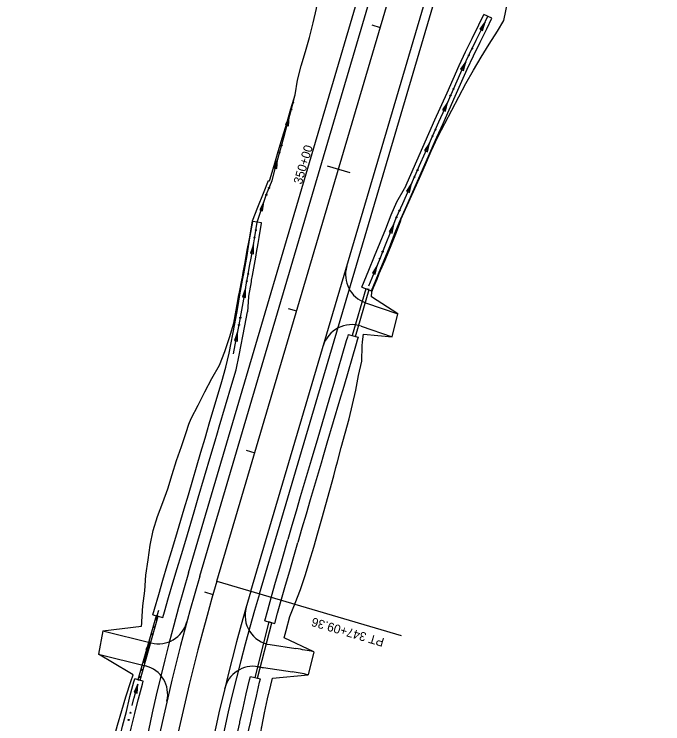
# Model space of a CAD drawing. Extents: x 948761 to 996004, y 1858548 to 1925175.
# Drawn here: x 960907.5 to 961346.2, y 1905677.2 to 1906157.3 of the extents above; entities that cross this region are included whole.
import ezdxf

# ---------------------------------------------------------------- set-up
doc = ezdxf.new("R2010")
doc.units = 0
for name, color, linetype in [('62', 7, 'Continuous'), ('R_Drainage', 7, 'Continuous'), ('R_Horz Alg', 7, 'Continuous'), ('R_Horz Alg Annot', 7, 'Continuous'), ('R_Proposed Const Limits', 7, 'Continuous'), ('R_Proposed Road', 7, 'Continuous')]:
    doc.layers.add(name, color=color, linetype=linetype)

msp = doc.modelspace()

# ---------------------------------------------------------------- linework, layer by layer
at = {"layer": '62'}
for p, q in [((961230.5, 1906154.53), (961225.1, 1906157.14)), ((961225.97, 1906152.06), (961222.4, 1906147.12)), ((961224.31, 1906146.2), (961225.97, 1906152.06)), ((961222.4, 1906147.12), (961224.31, 1906146.2)), ((961212.92, 1906125), (961209.4, 1906120.03)), ((961211.31, 1906119.13), (961212.92, 1906125)), ((961209.4, 1906120.03), (961211.31, 1906119.13)), ((961200.62, 1906097.6), (961197.21, 1906092.55)), ((961199.14, 1906091.69), (961200.62, 1906097.6)), ((961197.21, 1906092.55), (961199.14, 1906091.69)), ((961093.58, 1906087.87), (961090.99, 1906082.36)), ((961093.03, 1906081.81), (961093.58, 1906087.87)), ((961090.99, 1906082.36), (961093.03, 1906081.81)), ((961188.42, 1906070.15), (961185.02, 1906065.1)), ((961186.95, 1906064.24), (961188.42, 1906070.15)), ((961185.02, 1906065.1), (961186.95, 1906064.24)), ((961085.69, 1906058.89), (961083.13, 1906053.36)), ((961085.18, 1906052.82), (961085.69, 1906058.89)), ((961083.13, 1906053.36), (961085.18, 1906052.82)), ((961176.28, 1906042.68), (961172.91, 1906037.6)), ((961174.85, 1906036.75), (961176.28, 1906042.68)), ((961166.4, 1906030.35), (961171.51, 1906039.27)), ((961172.91, 1906037.6), (961174.85, 1906036.75)), ((961076.46, 1906030.36), (961073.55, 1906025)), ((961075.56, 1906024.33), (961076.46, 1906030.36)), ((961073.55, 1906025), (961075.56, 1906024.33)), ((961074.83, 1906016.04), (961068.87, 1906017.04)), ((961164.25, 1906015.16), (961161.09, 1906009.95)), ((961163.06, 1906009.18), (961164.25, 1906015.16)), ((961161.09, 1906009.95), (961163.06, 1906009.18)), ((961069.28, 1906001.29), (961067.25, 1905995.54)), ((961069.34, 1905995.19), (961069.28, 1906001.29)), ((961067.25, 1905995.54), (961069.34, 1905995.19)), ((961152.99, 1905987.31), (961149.75, 1905982.15)), ((961151.71, 1905981.35), (961152.99, 1905987.31)), ((961149.75, 1905982.15), (961151.71, 1905981.35)), ((961064.05, 1905971.71), (961061.94, 1905965.99)), ((961064.02, 1905965.62), (961064.05, 1905971.71)), ((961142.71, 1905972.67), (961149.2, 1905970.03)), ((961061.94, 1905965.99), (961064.02, 1905965.62)), ((961066.08, 1905966.11), (961065.28, 1905955.92)), ((961058.64, 1905942.16), (961056.48, 1905936.46)), ((961058.56, 1905936.07), (961058.64, 1905942.16)), ((961133.45, 1905940.7), (961132.86, 1905938.7)), ((961133.45, 1905940.7), (961140.16, 1905938.72)), ((961056.48, 1905936.46), (961058.56, 1905936.07)), ((961132.12, 1905936.2), (961123.64, 1905907.43)), ((961132.86, 1905938.7), (961132.12, 1905936.2)), ((961139.58, 1905936.72), (961138.84, 1905934.22)), ((961140.16, 1905938.72), (961139.58, 1905936.72)), ((961138.84, 1905934.22), (961130.35, 1905905.45)), ((961123.64, 1905907.43), (961120.81, 1905897.83)), ((961130.35, 1905905.45), (961127.52, 1905895.85)), ((961120.81, 1905897.83), (961112.32, 1905869.06)), ((961127.52, 1905895.85), (961119.03, 1905867.08)), ((961112.32, 1905869.06), (961109.49, 1905859.47)), ((961119.03, 1905867.08), (961116.2, 1905857.49)), ((961109.49, 1905859.47), (961108.34, 1905855.57)), ((961108.34, 1905855.57), (961101, 1905830.69)), ((961115.02, 1905853.47), (961107.72, 1905828.71)), ((961108.34, 1905855.57), (961108.34, 1905855.57)), ((961116.2, 1905857.49), (961115.02, 1905853.48)), ((961115.02, 1905853.48), (961115.02, 1905853.47)), ((961089.87, 1905792.24), (961092.63, 1905801.86)), ((961096.6, 1905790.31), (961099.36, 1905799.92)), ((961087.11, 1905782.63), (961089.87, 1905792.24)), ((961093.84, 1905780.7), (961096.6, 1905790.31)), ((961084.35, 1905773.02), (961087.11, 1905782.63)), ((961091.08, 1905771.09), (961093.84, 1905780.7)), ((961081.6, 1905763.4), (961084.35, 1905773.02)), ((961088.33, 1905761.48), (961091.08, 1905771.09)), ((961078.95, 1905754.02), (961081.6, 1905763.4)), ((961085.69, 1905752.14), (961088.33, 1905761.48)), ((961008.08, 1905749.1), (961009.17, 1905752.85)), ((961076.99, 1905746.92), (961078.95, 1905754.02)), ((961001.32, 1905750.92), (961008.08, 1905749.1)), ((961083.74, 1905745.06), (961085.69, 1905752.14)), ((961076.99, 1905746.92), (961083.74, 1905745.06)), ((960999.21, 1905732.98), (960996.54, 1905727.51)), ((960998.57, 1905726.92), (960999.21, 1905732.98)), ((960996.54, 1905727.51), (960998.57, 1905726.92)), ((961067.3, 1905709.27), (961074.1, 1905707.61)), ((960994.85, 1905706.09), (960989.03, 1905707.59)), ((960991.19, 1905704.04), (960988.6, 1905698.52)), ((960990.64, 1905697.97), (960991.19, 1905704.04)), ((960988.6, 1905698.52), (960990.64, 1905697.97))]:
    msp.add_line(p, q, dxfattribs=at)
for points in [[(961147.34, 1905973.42), (961149.61, 1905978.99), (961151.13, 1905982.72), (961154.92, 1905992.03), (961158.71, 1906001.34), (961162.5, 1906010.65), (961166.13, 1906020), (961170.28, 1906029.21), (961174.42, 1906038.41), (961178.45, 1906047.65), (961182.53, 1906056.87), (961186.62, 1906066.09), (961190.71, 1906075.31), (961194.8, 1906084.53), (961198.9, 1906093.75), (961203, 1906102.96), (961207.11, 1906112.18), (961211.21, 1906121.39), (961215.54, 1906130.54), (961219.96, 1906139.66), (961224.38, 1906148.78), (961227.92, 1906156.08)], [(961171.51, 1906039.27), (961171.67, 1906039.63), (961175.7, 1906048.85), (961179.79, 1906058.09), (961183.87, 1906067.31), (961187.96, 1906076.53), (961192.05, 1906085.75), (961200.26, 1906104.18), (961208.48, 1906122.64), (961212.83, 1906131.84), (961217.26, 1906140.97), (961221.68, 1906150.09), (961225.1, 1906157.14)], [(961149.2, 1905970.03), (961153.91, 1905981.59), (961157.7, 1905990.9), (961161.49, 1906000.21), (961165.28, 1906009.54), (961168.9, 1906018.84), (961173.01, 1906027.97), (961177.16, 1906037.19), (961181.19, 1906046.44), (961185.27, 1906055.65), (961189.36, 1906064.87), (961193.45, 1906074.09), (961197.54, 1906083.31), (961205.74, 1906101.74), (961213.94, 1906120.14), (961218.24, 1906129.24), (961222.66, 1906138.35), (961227.08, 1906147.47), (961230.5, 1906154.53)], [(961219.43, 1906138.56), (961219.96, 1906139.66), (961224.38, 1906148.78), (961225.97, 1906152.06)], [(961219.41, 1906138.53), (961219.43, 1906138.56)], [(961206.73, 1906111.34), (961207.11, 1906112.18), (961211.21, 1906121.39), (961212.92, 1906125)], [(961206.72, 1906111.3), (961206.73, 1906111.34)], [(961055.84, 1905927.42), (961057.72, 1905937.3), (961059.6, 1905947.17), (961061.42, 1905957.06), (961061.87, 1905959.64), (961063.18, 1905966.91), (961063.19, 1905966.96), (961064.97, 1905976.86), (961065.15, 1905977.85), (961065.74, 1905981.12), (961066.76, 1905986.76), (961067.96, 1905993.46), (961068.51, 1905996.67), (961069.51, 1906002.62), (961070.17, 1906006.6), (961071.83, 1906016.54), (961075.01, 1906026.03), (961078.19, 1906035.52), (961081.97, 1906044.83), (961084.53, 1906054.5), (961087.09, 1906064.17), (961089.77, 1906073.81), (961092.38, 1906083.46), (961095, 1906093.11), (961097.61, 1906102.77)], [(961097.51, 1906102.39), (961097.61, 1906102.77)], [(961097.5, 1906102.35), (961097.51, 1906102.39)], [(961194.52, 1906083.9), (961194.8, 1906084.53), (961198.9, 1906093.75), (961200.62, 1906097.6)], [(961089.65, 1906073.4), (961089.77, 1906073.81), (961092.38, 1906083.46), (961093.58, 1906087.87)], [(961194.5, 1906083.86), (961194.52, 1906083.9)], [(961089.64, 1906073.36), (961089.65, 1906073.4)], [(961182.34, 1906056.44), (961182.53, 1906056.87), (961186.62, 1906066.09), (961188.42, 1906070.15)], [(961081.8, 1906044.41), (961081.97, 1906044.83), (961084.53, 1906054.5), (961085.69, 1906058.89)], [(961182.32, 1906056.4), (961182.34, 1906056.44)], [(961081.78, 1906044.37), (961081.8, 1906044.41)], [(961170.17, 1906028.98), (961170.28, 1906029.21), (961174.42, 1906038.41), (961176.28, 1906042.68)], [(961071.76, 1906016.12), (961071.83, 1906016.54), (961075.01, 1906026.03), (961076.46, 1906030.36)], [(961142.71, 1905972.67), (961147.42, 1905984.23), (961151.21, 1905993.54), (961155, 1906002.85), (961158.78, 1906012.13), (961162.44, 1906021.55), (961166.4, 1906030.35)], [(961170.16, 1906028.94), (961170.17, 1906028.97)], [(961001.32, 1905750.92), (961002.45, 1905754.8), (961005.25, 1905764.63), (961008.13, 1905774.47), (961011.07, 1905784.26), (961013.98, 1905793.83), (961016.84, 1905803.4), (961022.5, 1905822.57), (961025.33, 1905832.17), (961033.81, 1905860.94), (961036.64, 1905870.53), (961038.3, 1905876.16), (961038.31, 1905876.18), (961039.47, 1905880.12), (961047.96, 1905908.9), (961050.76, 1905918.39), (961052.9, 1905928.03), (961056.65, 1905947.72), (961058.47, 1905957.59), (961058.92, 1905960.17), (961060.23, 1905967.45), (961060.24, 1905967.5), (961062.02, 1905977.39), (961062.2, 1905978.38), (961062.79, 1905981.65), (961065.01, 1905993.98), (961065.55, 1905997.17), (961066.55, 1906003.11), (961067.21, 1906007.1), (961068.87, 1906017.04)], [(961002.45, 1905754.79), (961005.25, 1905764.63), (961008.13, 1905774.47), (961011.07, 1905784.26), (961013.98, 1905793.83), (961016.84, 1905803.4), (961022.5, 1905822.57), (961025.33, 1905832.17), (961033.81, 1905860.94), (961036.64, 1905870.53), (961038.3, 1905876.16), (961038.31, 1905876.18), (961039.47, 1905880.12), (961047.96, 1905908.9), (961050.76, 1905918.39), (961052.9, 1905928.03), (961056.65, 1905947.72), (961058.47, 1905957.59), (961058.92, 1905960.17), (961060.23, 1905967.45), (961060.24, 1905967.5), (961062.02, 1905977.39), (961062.2, 1905978.38), (961062.79, 1905981.65), (961065.01, 1905993.98), (961065.55, 1905997.17), (961066.55, 1906003.11), (961067.21, 1906007.1), (961068.87, 1906017.04)], [(961066.08, 1905966.11), (961066.13, 1905966.37), (961066.14, 1905966.42), (961067.93, 1905976.33), (961068.1, 1905977.32), (961068.69, 1905980.58), (961070.92, 1905992.94), (961071.47, 1905996.17), (961072.47, 1906002.13), (961073.13, 1906006.11), (961074.75, 1906015.81), (961074.83, 1906016.04)], [(961071.76, 1906016.08), (961071.76, 1906016.12)], [(961158.67, 1906001.24), (961158.71, 1906001.34), (961162.5, 1906010.65), (961164.25, 1906015.16)], [(961066.71, 1905986.51), (961066.76, 1905986.76), (961067.96, 1905993.46), (961068.51, 1905996.67), (961069.28, 1906001.29)], [(961158.65, 1906001.2), (961158.67, 1906001.24)], [(961066.71, 1905986.47), (961066.71, 1905986.51)], [(961147.34, 1905973.42), (961149.61, 1905978.99), (961151.13, 1905982.72), (961152.99, 1905987.31)], [(961061.4, 1905956.94), (961061.42, 1905957.06), (961061.87, 1905959.64), (961063.18, 1905966.91), (961063.19, 1905966.96), (961064.05, 1905971.71)], [(961009.18, 1905752.87), (961011.98, 1905762.69), (961014.84, 1905772.48), (961017.77, 1905782.24), (961020.68, 1905791.81), (961023.55, 1905801.4), (961029.21, 1905820.59), (961032.04, 1905830.19), (961040.53, 1905858.96), (961043.36, 1905868.55), (961045.01, 1905874.16), (961045.01, 1905874.17), (961046.19, 1905878.14), (961054.67, 1905906.92), (961057.54, 1905916.64), (961059.76, 1905926.62), (961063.53, 1905946.43), (961065.28, 1905955.92)], [(961061.39, 1905956.91), (961061.4, 1905956.94)], [(961055.84, 1905927.42), (961057.72, 1905937.3), (961058.64, 1905942.16)], [(961101, 1905830.69), (961098.17, 1905821.09), (961095.39, 1905811.47), (961092.63, 1905801.86)], [(961107.72, 1905828.71), (961104.89, 1905819.13), (961102.12, 1905809.53), (961099.36, 1905799.92)], [(961003.42, 1905747.42), (961005.33, 1905753.97)], [(961003.41, 1905747.38), (961003.42, 1905747.42)], [(960995.11, 1905718.55), (960996.77, 1905724.49), (960999.21, 1905732.98)], [(960995.1, 1905718.52), (960995.11, 1905718.55)], [(961045.08, 1905602.51), (961046.7, 1905611.8), (961048.43, 1905621.37), (961050.23, 1905630.93), (961052.1, 1905640.47), (961054.03, 1905650.01), (961056.03, 1905659.52), (961058.09, 1905669.03), (961060.08, 1905677.88), (961060.21, 1905678.49), (961062.31, 1905687.98), (961064.48, 1905697.46), (961066.72, 1905706.93), (961067.3, 1905709.27)], [(960964.04, 1905584.87), (960965.64, 1905594.93), (960967.35, 1905605.06), (960970.92, 1905625.24), (960972.69, 1905635.34), (960974.56, 1905645.44), (960976.52, 1905655.52), (960978.59, 1905665.6), (960980.83, 1905675.67), (960983.38, 1905685.62), (960985.53, 1905694.57), (960985.53, 1905694.61), (960985.8, 1905695.63), (960988.48, 1905705.51), (960989.03, 1905707.59)], [(960969.98, 1905584.02), (960971.57, 1905593.96), (960973.27, 1905604.04), (960976.83, 1905624.2), (960978.59, 1905634.28), (960980.45, 1905644.32), (960982.4, 1905654.35), (960984.46, 1905664.34), (960986.66, 1905674.27), (960989.2, 1905684.17), (960991.44, 1905693.48), (960991.59, 1905694.07), (960994.28, 1905703.96), (960994.85, 1905706.09)], [(961051.98, 1905601.31), (961053.59, 1905610.58), (961055.32, 1905620.1), (961057.11, 1905629.61), (961058.96, 1905639.11), (961060.89, 1905648.59), (961062.87, 1905658.06), (961064.93, 1905667.52), (961066.92, 1905676.37), (961067.05, 1905676.99), (961069.14, 1905686.44), (961071.3, 1905695.87), (961073.53, 1905705.29), (961074.1, 1905707.61)], [(960987.4, 1905689.52), (960988.53, 1905694.21), (960988.53, 1905694.22), (960988.7, 1905694.85), (960991.19, 1905704.04)], [(960987.39, 1905689.49), (960987.4, 1905689.52)]]:
    msp.add_lwpolyline(points, dxfattribs=at)
for centre in [(961217.2, 1906134.06), (961215.03, 1906129.54), (961204.66, 1906106.76), (961096.16, 1906097.55), (961202.62, 1906102.19), (961094.85, 1906092.72), (961192.45, 1906079.32), (961190.41, 1906074.74), (961088.27, 1906068.57), (961086.94, 1906063.74), (961180.27, 1906051.86), (961178.24, 1906047.28), (961078.02, 1906035.12), (961079.88, 1906039.77), (961168.08, 1906024.41), (961166.03, 1906019.84), (961070.9, 1906011.17), (961070.07, 1906006.23), (961154.85, 1905991.96), (961156.74, 1905996.6), (961065.79, 1905981.57), (961064.9, 1905976.64), (961060.45, 1905952.01), (961059.55, 1905947.08), (961001.98, 1905742.61), (961000.57, 1905737.8), (960993.73, 1905713.72), (960992.45, 1905708.88), (960986.19, 1905684.65), (960984.95, 1905679.8)]:
    msp.add_circle(centre, 0.375, dxfattribs=at)
at = {"layer": 'R_Drainage'}
for p, q in [((961145.38, 1905971.58), (961136.16, 1905939.89)), ((961138.4, 1905939.24), (961147.62, 1905970.93)), ((961147.62, 1905970.93), (961145.38, 1905971.58)), ((961136.16, 1905939.89), (961138.4, 1905939.24)), ((961003.5, 1905750.34), (960991.21, 1905707.01)), ((960992.65, 1905706.6), (961004.94, 1905749.94)), ((961004.94, 1905749.94), (961003.5, 1905750.34)), ((961079.79, 1905746.08), (961070.21, 1905708.57)), ((961072.15, 1905708.07), (961081.73, 1905745.59)), ((961081.73, 1905745.59), (961079.79, 1905746.08)), ((960991.21, 1905707.01), (960992.65, 1905706.6)), ((961070.21, 1905708.57), (961072.15, 1905708.07))]:
    msp.add_line(p, q, dxfattribs=at)
at = {"layer": 'R_Horz Alg'}
msp.add_line((961044.57, 1905773.69), (961317.38, 1906698.54), dxfattribs=at)
msp.add_arc((962418.44, 1905368.43), 1432.39, 163.56518, 178.98802, dxfattribs=at)
at = {"layer": 'R_Horz Alg Annot'}
for points in [[(961149.33, 1906150.07), (961155.09, 1906148.37)], [(961119.12, 1906054.72), (961134.47, 1906050.19)], [(961092.75, 1905958.24), (961098.5, 1905956.54)], [(961064.46, 1905862.33), (961070.21, 1905860.63)], [(961044.57, 1905773.69), (961169.26, 1905736.91)], [(961036.18, 1905766.37), (961041.95, 1905764.71)]]:
    msp.add_lwpolyline(points, dxfattribs=at)
at = {"layer": 'R_Proposed Const Limits'}
for points in [[(961238.56, 1906152.94), (961244.22, 1906180.47), (961242.85, 1906185.04), (961239.44, 1906196.47), (961237.18, 1906205.31), (961236.23, 1906218.81), (961234.68, 1906229.43), (961234.02, 1906239.77), (961232.44, 1906250.67)], [(961097.56, 1906102.79), (961099.09, 1906112.76), (961101.69, 1906122.42), (961104.43, 1906132.04), (961107.19, 1906141.65), (961109.61, 1906151.36), (961112.05, 1906161.07), (961113.31, 1906171.12), (961108.61, 1906182.93), (961092.77, 1906221.89)], [(961149.35, 1905969.45), (961150.5, 1905972.32), (961153.08, 1905977.94), (961154.38, 1905981.78), (961158.45, 1905990.81), (961162.54, 1906000.83), (961165.96, 1906009.76), (961168.93, 1906017.78), (961169.24, 1906018.78), (961173.34, 1906027.94), (961177.67, 1906037.4), (961181.53, 1906046.32), (961185.72, 1906055.62), (961189.53, 1906064.57), (961194.12, 1906074.3), (961198.83, 1906083.34), (961203.56, 1906092.37), (961208.24, 1906101.42), (961213, 1906110.44), (961218.1, 1906119.36), (961223.36, 1906128.23), (961228.81, 1906137.05), (961234.27, 1906145.87), (961238.56, 1906152.94)], [(961046.29, 1905919.82), (961049.9, 1905929.18), (961053.2, 1905938.63), (961055.98, 1905948.23), (961057.64, 1905957.15), (961058.32, 1905960.84), (961059.44, 1905967.45), (961059.92, 1905969.15), (961061.48, 1905977.44), (961061.89, 1905979.42), (961062.41, 1905982.54), (961063.47, 1905988.17), (961064.61, 1905994.66), (961065.07, 1905997.66), (961066.35, 1906004.12), (961067.06, 1906007.74), (961068.64, 1906017.48), (961072.37, 1906026.81), (961076.17, 1906036.11), (961079.54, 1906044.88), (961079.54, 1906044.88), (961080.27, 1906044.67), (961080.45, 1906045.28), (961083.25, 1906054.88), (961086.04, 1906064.48), (961088.94, 1906074.05), (961091.81, 1906083.63), (961094.67, 1906093.21), (961097.56, 1906102.79)], [(961166.96, 1905954.67), (961149.27, 1905966.05), (961149.35, 1905969.45)], [(961110.13, 1905725.93), (961090.2, 1905735.44), (961091.54, 1905740.42), (961094.03, 1905749.71), (961097.56, 1905758.73), (961101.07, 1905768.12), (961104.29, 1905777.59), (961107.17, 1905787.17), (961110.06, 1905796.75), (961112.81, 1905806.36), (961115.54, 1905815.98), (961118.35, 1905825.58), (961121.07, 1905835.2), (961123.66, 1905844.86), (961125.11, 1905850.54), (961125.11, 1905850.55), (961126.2, 1905854.54), (961128.74, 1905864.22), (961131.31, 1905873.89), (961134, 1905883.52), (961136.3, 1905893.26), (961138.58, 1905903.02), (961140.41, 1905912.91), (961142.73, 1905922.65), (961142.89, 1905933.03), (961143.07, 1905935.69), (961143.66, 1905940.9), (961163.09, 1905939.09)], [(960994.51, 1905756.92), (960995.87, 1905767.24), (960996.66, 1905777.74), (960998.23, 1905788.03), (960999.48, 1905798.09), (961001.58, 1905807.89), (961004.45, 1905817.47), (961008.08, 1905826.83), (961011.51, 1905836.24), (961014.42, 1905845.81), (961017.36, 1905855.37), (961020.61, 1905864.83), (961023.73, 1905874.34), (961025.54, 1905879.93), (961027.26, 1905883.73), (961031.89, 1905892.79), (961036.44, 1905901.87), (961041.09, 1905910.92), (961046.29, 1905919.82)], [(960967.46, 1905740.07), (960993.71, 1905743.22), (960993.85, 1905745.37), (960993.9, 1905746.42), (960994.51, 1905756.92)], [(960907.55, 1905560.62), (960959.78, 1905572.57), (960959.84, 1905574.99), (960959.43, 1905575.95), (960959.23, 1905578.82), (960959.8, 1905585.4), (960960.94, 1905595.64), (960962.97, 1905605.74), (960964.85, 1905615.86), (960966.86, 1905625.96), (960968.83, 1905636.07), (960970.77, 1905646.17), (960972.63, 1905656.29), (960974.65, 1905666.39), (960977.33, 1905676.34), (960980.38, 1905686.2), (960983.07, 1905695.46), (960983.28, 1905696.08), (960983.28, 1905696.08), (960986.48, 1905705.89), (960987.95, 1905710.39), (960985.67, 1905711.7), (960964.54, 1905724.31)], [(961076.88, 1905574.16), (961058.15, 1905588.04), (961058.46, 1905590.17), (961060.42, 1905599.6), (961062.37, 1905609.02), (961064.3, 1905618.44), (961066.27, 1905627.85), (961068.25, 1905637.26), (961070.29, 1905646.65), (961072.5, 1905656.01), (961073.93, 1905665.53), (961074.85, 1905674.55), (961074.85, 1905674.55), (961074.94, 1905675.16), (961076.7, 1905684.63), (961078.88, 1905694), (961081.05, 1905703.38), (961082.23, 1905708.07), (961106.26, 1905710.39)]]:
    msp.add_lwpolyline(points, dxfattribs=at)
at = {"layer": 'R_Proposed Road'}
for p, q in [((961025.38, 1905779.35), (961298.19, 1906704.2)), ((961033.06, 1905777.09), (961305.87, 1906701.94)), ((961067.59, 1905766.9), (961340.4, 1906691.75)), ((961073.34, 1905765.2), (961346.15, 1906690.06)), ((961145.15, 1905962.11), (961166.96, 1905954.67)), ((961163.09, 1905939.09), (961166.96, 1905954.67)), ((961142.2, 1905946.21), (961163.09, 1905939.09)), ((960967.46, 1905740.07), (960964.54, 1905724.31)), ((960967.46, 1905740.07), (961000.12, 1905731.9)), ((961080.62, 1905730.74), (961098.06, 1905728.07)), ((960964.54, 1905724.31), (960996.23, 1905716.37)), ((961110.13, 1905725.93), (961106.26, 1905710.39)), ((961076.05, 1905715.26), (961095.64, 1905712.25))]:
    msp.add_line(p, q, dxfattribs=at)
for centre, radius, start, end in [((961151.6, 1905981.04), 20, 163.5652, 251.1698), ((961135.75, 1905927.28), 20, 71.1698, 163.5652), ((962418.44, 1905368.43), 1452.39, 163.56518, 178.98802), ((962418.44, 1905368.43), 1444.39, 163.56518, 178.98802), ((962418.44, 1905368.43), 1408.39, 163.56518, 178.98802), ((962418.44, 1905368.43), 1402.39, 163.56518, 178.98802), ((961083.65, 1905750.51), 20, 164.0263, 261.2848), ((961004.98, 1905751.3), 20, 255.9396, 344.844), ((961057.76, 1905465.14), 266, 78.6453, 81.2848), ((960991.37, 1905696.97), 20, 347.0351, 75.9396), ((961069.26, 1905696.1), 20, 80.058, 166.3489), ((961100, 1905871.43), 158, 260.058, 261.2848), ((961057.76, 1905465.14), 250, 78.8117, 81.2848)]:
    msp.add_arc(centre, radius, start, end, dxfattribs=at)

# ---------------------------------------------------------------- texts
at = {"layer": 'R_Horz Alg'}
msp.add_text('+', height=1, rotation=73.5652, dxfattribs=at).set_placement((961045.05, 1905773.55))
at = {"layer": 'R_Horz Alg Annot'}
for s, rotation, p in [('350+00', 73.5652, (961101.98, 1906041.8)), ('PT 347+09.36', 163.5652, (961158.25, 1905734.94))]:
    msp.add_text(s, height=6, rotation=rotation, dxfattribs=at).set_placement(p)

doc.saveas('drawing.dxf')
